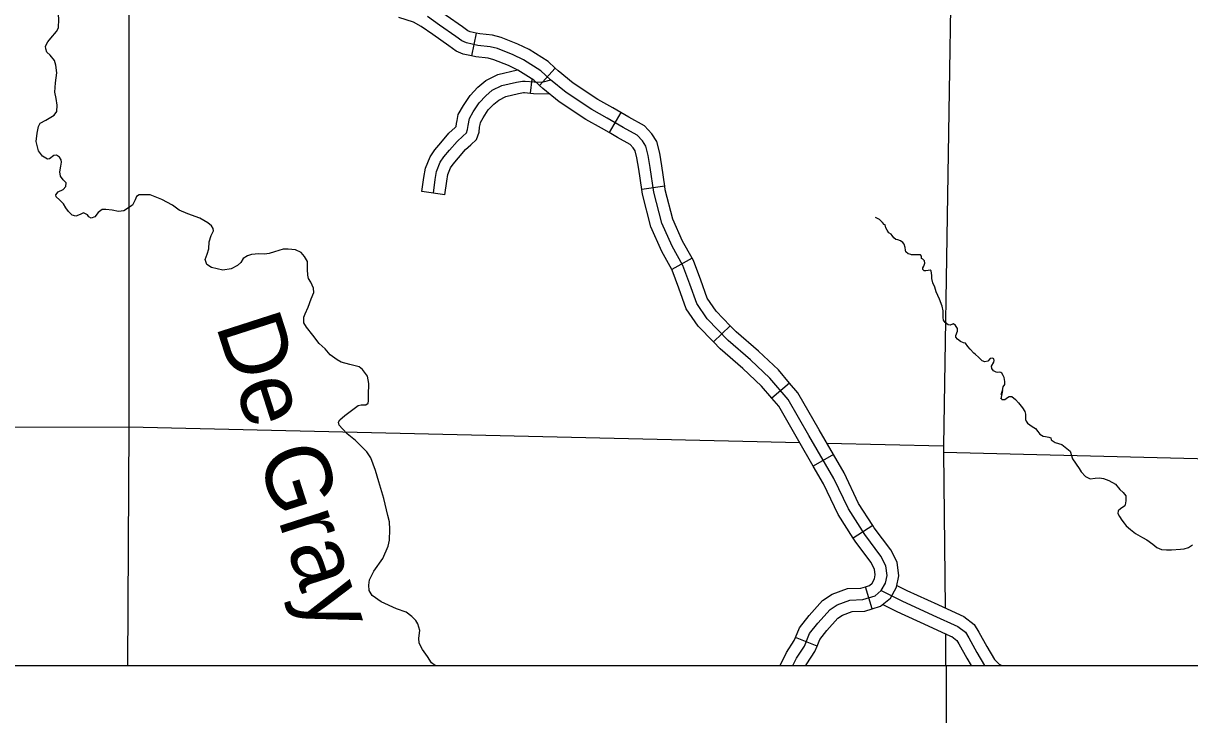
# Model space of a CAD drawing. Extents: x 1373862 to 1377080, y 1164775 to 1170415.
# Drawn here: x 1375030.3 to 1375152.2, y 1168588.7 to 1168661 of the extents above; entities that cross this region are included whole.
import ezdxf

# ---------------------------------------------------------------- set-up
doc = ezdxf.new("R2010")
doc.units = 0
for name, color, linetype in [('1', 7, 'Continuous'), ('Level 32', 7, 'Continuous'), ('Level 35', 7, 'Continuous'), ('Level 4', 7, 'Continuous'), ('Level 45', 7, 'Continuous'), ('Level 5', 7, 'Continuous'), ('R_Dimension', 7, 'Continuous')]:
    doc.layers.add(name, color=color, linetype=linetype)

msp = doc.modelspace()

# ---------------------------------------------------------------- linework, layer by layer
at = {"layer": '1'}
msp.add_lwpolyline([(1376107.39, 1169553.54), (1374750.71, 1169553.54), (1374750.71, 1168593.87), (1376107.39, 1168593.87)], close=True, dxfattribs=at)
at = {"layer": 'Level 32'}
for p, q in [((1375077.62, 1168659.94), (1375077.11, 1168657.57)), ((1375085.87, 1168656.27), (1375084.24, 1168654.47)), ((1375092.73, 1168651.63), (1375091.5, 1168649.54)), ((1375097.32, 1168643.96), (1375094.91, 1168643.61)), ((1375100.18, 1168636.44), (1375098.06, 1168635.24)), ((1375104.15, 1168629.37), (1375102.41, 1168627.68)), ((1375110.35, 1168623.39), (1375108.51, 1168621.81)), ((1375114.94, 1168615.93), (1375112.84, 1168614.71)), ((1375119.05, 1168608.49), (1375117, 1168607.19)), ((1375119.01, 1168599.79), (1375118.28, 1168602.11)), ((1375113.23, 1168595.89), (1375110.98, 1168596.82))]:
    msp.add_line(p, q, dxfattribs=at)
for points in [[(1375077.11, 1168657.57), (1375076.25, 1168657.75), (1375075.51, 1168658.05), (1375074.77, 1168658.62), (1375073.08, 1168659.78), (1375071.86, 1168660.64), (1375071.07, 1168661.09), (1375069.54, 1168661.56)], [(1375077.62, 1168659.94), (1375076.97, 1168660.08), (1375076.73, 1168660.18), (1375076.2, 1168660.59), (1375074.47, 1168661.78), (1375073.98, 1168662.12)], [(1375085.87, 1168656.27), (1375085.12, 1168656.96), (1375083.16, 1168658.21), (1375081.97, 1168658.78), (1375080.22, 1168659.48), (1375079.31, 1168659.72), (1375077.98, 1168659.86), (1375077.62, 1168659.94)], [(1375084.24, 1168654.47), (1375083.63, 1168655.02), (1375081.97, 1168656.08), (1375081, 1168656.56), (1375079.46, 1168657.16), (1375078.86, 1168657.32), (1375077.59, 1168657.46), (1375077.11, 1168657.57)], [(1375092.73, 1168651.63), (1375091.91, 1168652.12), (1375090.33, 1168653), (1375087.74, 1168654.72), (1375086.18, 1168655.99), (1375085.87, 1168656.27)], [(1375091.5, 1168649.54), (1375090.7, 1168650.01), (1375089.06, 1168650.93), (1375086.3, 1168652.76), (1375084.59, 1168654.14), (1375084.24, 1168654.47)], [(1375097.32, 1168643.96), (1375097, 1168646.09), (1375096.79, 1168647.41), (1375096.48, 1168648.6), (1375095.98, 1168649.41), (1375095.2, 1168650.26), (1375093.56, 1168651.15), (1375092.73, 1168651.63)], [(1375094.91, 1168643.61), (1375094.6, 1168645.73), (1375094.41, 1168646.91), (1375094.22, 1168647.63), (1375094.03, 1168647.94), (1375093.69, 1168648.32), (1375092.37, 1168649.03), (1375091.5, 1168649.54)], [(1375098.06, 1168635.24), (1375097.01, 1168637.12), (1375095.86, 1168639.69), (1375094.99, 1168643.1), (1375094.91, 1168643.61)], [(1375100.18, 1168636.44), (1375099.18, 1168638.21), (1375098.16, 1168640.49), (1375097.37, 1168643.58), (1375097.32, 1168643.96)], [(1375104.15, 1168629.37), (1375102.69, 1168630.88), (1375101.75, 1168632.26), (1375101.08, 1168634.14), (1375100.32, 1168636.19), (1375100.18, 1168636.44)], [(1375102.41, 1168627.68), (1375100.8, 1168629.34), (1375099.57, 1168631.15), (1375098.79, 1168633.31), (1375098.11, 1168635.17), (1375098.06, 1168635.24)], [(1375110.35, 1168623.39), (1375109.19, 1168624.75), (1375107.1, 1168626.73), (1375104.78, 1168628.72), (1375104.15, 1168629.37)], [(1375108.51, 1168621.81), (1375107.43, 1168623.07), (1375105.47, 1168624.92), (1375103.11, 1168626.95), (1375102.41, 1168627.68)], [(1375114.94, 1168615.93), (1375113.44, 1168618.51), (1375111.22, 1168622.37), (1375110.35, 1168623.39)], [(1375112.84, 1168614.71), (1375111.34, 1168617.3), (1375109.23, 1168620.96), (1375108.51, 1168621.81)], [(1375119.05, 1168608.49), (1375117.57, 1168610.82), (1375116.07, 1168613.99), (1375114.94, 1168615.93)], [(1375117, 1168607.19), (1375115.44, 1168609.64), (1375113.92, 1168612.86), (1375112.84, 1168614.71)], [(1375119.01, 1168599.79), (1375119.88, 1168600.07), (1375120.9, 1168600.91), (1375121.52, 1168602.06), (1375121.79, 1168603.24), (1375121.59, 1168604.67), (1375120.94, 1168605.96), (1375119.21, 1168608.25), (1375119.05, 1168608.49)], [(1375118.28, 1168602.11), (1375118.7, 1168602.24), (1375118.98, 1168602.48), (1375119.23, 1168602.93), (1375119.32, 1168603.34), (1375119.24, 1168603.93), (1375118.87, 1168604.67), (1375117.21, 1168606.86), (1375117, 1168607.19)], [(1375110.98, 1168596.82), (1375111.41, 1168597.83), (1375112.4, 1168599.09), (1375113.8, 1168600.68), (1375114.8, 1168601.32), (1375116.42, 1168601.93), (1375117.82, 1168601.97), (1375118.28, 1168602.11)], [(1375113.23, 1168595.89), (1375113.52, 1168596.59), (1375114.26, 1168597.54), (1375115.39, 1168598.81), (1375115.9, 1168599.14), (1375116.89, 1168599.51), (1375118.23, 1168599.55), (1375119.01, 1168599.79)], [(1375109.37, 1168593.87), (1375110.03, 1168595.25), (1375110.84, 1168596.48), (1375110.98, 1168596.82)], [(1375112.06, 1168593.87), (1375112.15, 1168594.05), (1375113, 1168595.34), (1375113.23, 1168595.89)]]:
    msp.add_lwpolyline(points, dxfattribs=at)
at = {"layer": 'Level 35'}
for points in [[(1375033.15, 1168659.42), (1375033.76, 1168660.1), (1375033.97, 1168660.48), (1375034, 1168661.39), (1375033.93, 1168662.27), (1375033.58, 1168663.83), (1375033.26, 1168664.86), (1375032.62, 1168665.87), (1375032.1, 1168666.5), (1375031.54, 1168667.06), (1375030.64, 1168667.66), (1375030.46, 1168667.73)], [(1375033.04, 1168646.82), (1375032.83, 1168646.76), (1375032.29, 1168647.09), (1375031.86, 1168647.65), (1375031.63, 1168648.62), (1375031.73, 1168649.5), (1375031.86, 1168650.19), (1375032.06, 1168650.53), (1375032.64, 1168650.86), (1375033.5, 1168651.37), (1375033.78, 1168651.76), (1375033.84, 1168652.41), (1375033.71, 1168653.12), (1375033.58, 1168653.76), (1375033.65, 1168654.73), (1375033.78, 1168655.79), (1375033.69, 1168656.6), (1375033.56, 1168657.08), (1375033.09, 1168657.64), (1375032.75, 1168657.94), (1375032.66, 1168658.31), (1375032.62, 1168658.56), (1375032.85, 1168659.02), (1375033.15, 1168659.42)], [(1375048.74, 1168640.61), (1375047.48, 1168641.05), (1375046.59, 1168641.44), (1375045.88, 1168641.98), (1375044.77, 1168642.56), (1375043.56, 1168643.03), (1375042.85, 1168643.03), (1375042.38, 1168643.05), (1375042.12, 1168642.88), (1375041.97, 1168642.54), (1375041.69, 1168641.95), (1375040.79, 1168641.37), (1375040.25, 1168641.31), (1375039.58, 1168641.46), (1375038.91, 1168641.5), (1375038.53, 1168641.52), (1375038.1, 1168641.2), (1375037.77, 1168640.73), (1375037.39, 1168640.6), (1375037.13, 1168640.73), (1375036.98, 1168640.96), (1375036.59, 1168641.16), (1375036.22, 1168640.98), (1375035.79, 1168640.83), (1375035.41, 1168640.92), (1375035, 1168641.29), (1375034.74, 1168641.7), (1375034.5, 1168642.1), (1375034.07, 1168642.54), (1375033.73, 1168642.82), (1375033.69, 1168643.03), (1375033.94, 1168643.37), (1375034.44, 1168643.61), (1375034.74, 1168643.91), (1375034.76, 1168644.3), (1375034.44, 1168644.6), (1375034.18, 1168645.01), (1375034.09, 1168645.44), (1375034.2, 1168646.04), (1375034.27, 1168646.45), (1375034.25, 1168646.71), (1375034.07, 1168646.97), (1375033.75, 1168647.19), (1375033.47, 1168647.16), (1375033.04, 1168646.82)], [(1375060.37, 1168632.18), (1375060.64, 1168632.86), (1375060.62, 1168633.31), (1375060.34, 1168633.93), (1375060.1, 1168634.3), (1375060.01, 1168634.67), (1375059.99, 1168635.25), (1375059.99, 1168635.74), (1375059.99, 1168636.09), (1375059.69, 1168636.62), (1375059.32, 1168637.03), (1375058.74, 1168637.31), (1375057.97, 1168637.36), (1375057.43, 1168637.38), (1375056.53, 1168637.1), (1375055.99, 1168636.93), (1375055.5, 1168636.84), (1375054.91, 1168636.88), (1375054.12, 1168636.82), (1375053.71, 1168636.69), (1375053.26, 1168636.41), (1375053.02, 1168635.98), (1375052.68, 1168635.66), (1375052.01, 1168635.31), (1375051.13, 1168635.16), (1375049.97, 1168635.46), (1375049.45, 1168635.78), (1375049.3, 1168636.28), (1375049.49, 1168636.84), (1375049.67, 1168637.42), (1375049.71, 1168638.13), (1375049.92, 1168638.8), (1375050.16, 1168639.27), (1375050.12, 1168639.53), (1375049.97, 1168639.81), (1375049.56, 1168640.13), (1375048.74, 1168640.61)], [(1375131.47, 1168625.14), (1375131.7, 1168625.57), (1375131.74, 1168625.74), (1375131.72, 1168625.93), (1375131.57, 1168625.97), (1375131.34, 1168625.95), (1375131.07, 1168625.68), (1375130.75, 1168625.61), (1375130.5, 1168625.7), (1375130.1, 1168626.08), (1375129.78, 1168626.37), (1375129.63, 1168626.52), (1375129.25, 1168626.92), (1375129, 1168627.22), (1375128.74, 1168627.56), (1375128.55, 1168627.6), (1375128.22, 1168627.71), (1375127.9, 1168627.96), (1375127.75, 1168628.17), (1375127.75, 1168628.34), (1375127.9, 1168628.81), (1375127.9, 1168629.08), (1375127.69, 1168629.4), (1375127.48, 1168629.57), (1375127.39, 1168629.55), (1375127.14, 1168629.42), (1375126.95, 1168629.48), (1375126.61, 1168629.71), (1375126.46, 1168629.95), (1375126.42, 1168630.24), (1375126.42, 1168630.56), (1375126.4, 1168630.94), (1375126.31, 1168631.43), (1375126.02, 1168632.16), (1375125.68, 1168632.92), (1375125.55, 1168633.4), (1375125.34, 1168633.87), (1375125.24, 1168634.31), (1375125.22, 1168634.61), (1375125.15, 1168635.1), (1375125.05, 1168635.18), (1375124.86, 1168635.14), (1375124.6, 1168635.1), (1375124.43, 1168635.12), (1375124.29, 1168635.24), (1375124.29, 1168635.41), (1375124.39, 1168635.6), (1375124.48, 1168635.92), (1375124.46, 1168636.15), (1375124.29, 1168636.32), (1375124.16, 1168636.39), (1375124.14, 1168636.47), (1375124.14, 1168636.64), (1375124.04, 1168636.77), (1375123.91, 1168636.77), (1375123.64, 1168636.79), (1375123.42, 1168636.77), (1375123.11, 1168636.79), (1375123.02, 1168636.81), (1375122.77, 1168636.87), (1375122.52, 1168637.08), (1375122.47, 1168637.25), (1375122.45, 1168637.55), (1375122.33, 1168637.89), (1375122.2, 1168638.06), (1375121.95, 1168638.25), (1375121.67, 1168638.33), (1375121.48, 1168638.37), (1375121.25, 1168638.56), (1375121.08, 1168638.8), (1375120.97, 1168638.92), (1375120.72, 1168639.09), (1375120.55, 1168639.35), (1375120.42, 1168639.6), (1375120.34, 1168639.9), (1375120.26, 1168639.96), (1375120.06, 1168640.15), (1375119.75, 1168640.47), (1375119.35, 1168640.68)], [(1375065.28, 1168621.03), (1375065.58, 1168621.11), (1375065.84, 1168621.11), (1375066.07, 1168621.11), (1375066.33, 1168621.28), (1375066.37, 1168621.52), (1375066.37, 1168622.04), (1375066.35, 1168622.51), (1375066.4, 1168622.94), (1375066.4, 1168623.33), (1375066.27, 1168624.1), (1375065.75, 1168624.79), (1375065.39, 1168625.09), (1375064.4, 1168625.33), (1375063.49, 1168625.55), (1375063.1, 1168625.8), (1375062.37, 1168626.32), (1375061.84, 1168626.95), (1375061.19, 1168627.51), (1375060.54, 1168628.37), (1375059.88, 1168629.21), (1375059.62, 1168629.66), (1375059.62, 1168630.05), (1375059.6, 1168630.28), (1375059.73, 1168630.63), (1375060.05, 1168631.3), (1375060.37, 1168632.18)], [(1375132.46, 1168622.2), (1375132.63, 1168622.62), (1375132.69, 1168622.98), (1375132.84, 1168623.23), (1375132.84, 1168623.55), (1375132.8, 1168623.95), (1375132.69, 1168624.16), (1375132.55, 1168624.4), (1375132.44, 1168624.5), (1375132.34, 1168624.52), (1375132.1, 1168624.5), (1375131.96, 1168624.52), (1375131.66, 1168624.67), (1375131.51, 1168624.9), (1375131.47, 1168625.14)], [(1375132.63, 1168622.62), (1375132.44, 1168621.75), (1375132.46, 1168621.8), (1375132.55, 1168621.67), (1375132.84, 1168621.67), (1375133.12, 1168621.88), (1375133.31, 1168621.99), (1375133.58, 1168621.97), (1375133.98, 1168621.65), (1375134.28, 1168621.31), (1375134.7, 1168620.78), (1375134.93, 1168620.4), (1375135, 1168620.13), (1375135, 1168619.79), (1375135.02, 1168619.58), (1375135.08, 1168619.39), (1375135.21, 1168619.2), (1375135.72, 1168618.84), (1375136.05, 1168618.65), (1375136.29, 1168618.33), (1375136.52, 1168618.03), (1375136.88, 1168617.84), (1375137.11, 1168617.8), (1375137.47, 1168617.74), (1375137.66, 1168617.65), (1375137.7, 1168617.44), (1375138.12, 1168617.17), (1375138.8, 1168616.98)], [(1375068.38, 1168609.56), (1375067.95, 1168611.31), (1375067.45, 1168613.05), (1375067.08, 1168614.26), (1375066.61, 1168615.59), (1375066.2, 1168616.2), (1375065.58, 1168616.8), (1375065, 1168617.38), (1375064.12, 1168618.09), (1375063.66, 1168618.59), (1375063.28, 1168618.99), (1375063.21, 1168619.3), (1375063.36, 1168619.55), (1375063.88, 1168620.01), (1375064.87, 1168620.74), (1375065.28, 1168621.03)], [(1375138.8, 1168616.98), (1375139.69, 1168616.28), (1375139.92, 1168615.48), (1375140.62, 1168614.46), (1375140.85, 1168614.12), (1375141.29, 1168613.62), (1375141.78, 1168613.38), (1375142.31, 1168613.45), (1375142.75, 1168613.47), (1375143.17, 1168613.42), (1375143.72, 1168613.19), (1375144.42, 1168612.83), (1375144.88, 1168612.26), (1375145.24, 1168611.94), (1375145.5, 1168611.61), (1375145.5, 1168611.13), (1375145.47, 1168610.83), (1375145.39, 1168610.56), (1375144.93, 1168610.24), (1375144.69, 1168610.05), (1375144.67, 1168609.75), (1375144.84, 1168609.44), (1375145.09, 1168609.06), (1375145.33, 1168608.74), (1375145.52, 1168608.46), (1375145.98, 1168608.1), (1375146.51, 1168607.68), (1375147.25, 1168607.24), (1375147.71, 1168607.01), (1375148.34, 1168606.54), (1375148.74, 1168606.2), (1375149.23, 1168606.01), (1375149.76, 1168605.95), (1375150.29, 1168605.97), (1375151.2, 1168606.03), (1375151.6, 1168606.07), (1375152.04, 1168606.22), (1375152.46, 1168606.48)], [(1375067.67, 1168600.52), (1375066.76, 1168601.18), (1375066.44, 1168601.7), (1375066.4, 1168602.28), (1375066.46, 1168602.84), (1375066.91, 1168603.74), (1375067.86, 1168605.06), (1375068.4, 1168606.35), (1375068.57, 1168606.99), (1375068.59, 1168608.09), (1375068.57, 1168608.89), (1375068.38, 1168609.56)], [(1375073.34, 1168593.87), (1375072.94, 1168594.15), (1375072.53, 1168594.82), (1375072.01, 1168595.57), (1375071.67, 1168596.22), (1375071.62, 1168596.73), (1375071.71, 1168597.53), (1375071.5, 1168598.24), (1375071.32, 1168598.59), (1375070.89, 1168599), (1375070.31, 1168599.45), (1375069.3, 1168599.81), (1375067.67, 1168600.52)]]:
    msp.add_lwpolyline(points, dxfattribs=at)
at = {"layer": 'Level 4'}
for points in [[(1375128.05, 1168720.45), (1375127.81, 1168703.12), (1375127.79, 1168701.88), (1375126.45, 1168616.81), (1375126.45, 1168616.15), (1375126.61, 1168599.9)], [(1375126.64, 1168597.21), (1375126.67, 1168593.87)]]:
    msp.add_lwpolyline(points, dxfattribs=at)
at = {"layer": 'Level 45'}
for p, q in [((1375083.3, 1168653.66), (1375083.45, 1168655.14)), ((1375074.34, 1168643.06), (1375071.94, 1168643.4))]:
    msp.add_line(p, q, dxfattribs=at)
for points in [[(1375085.39, 1168655.07), (1375084.37, 1168655.99), (1375082.57, 1168657.14), (1375081.49, 1168657.67), (1375079.84, 1168658.32), (1375079.08, 1168658.52), (1375077.78, 1168658.66), (1375076.61, 1168658.92), (1375076.12, 1168659.12), (1375075.49, 1168659.6), (1375073.77, 1168660.78), (1375072.51, 1168661.66)], [(1375075.63, 1168650.82), (1375075.74, 1168651.43), (1375076.28, 1168652.37), (1375076.97, 1168653.43), (1375077.78, 1168654.28), (1375078.63, 1168655), (1375079.88, 1168655.61), (1375081.93, 1168656.1)], [(1375073.48, 1168645.49), (1375073.86, 1168646.45), (1375074.24, 1168647), (1375074.84, 1168647.7), (1375075.62, 1168648.62), (1375076.23, 1168649.18), (1375076.59, 1168649.51), (1375076.72, 1168649.87), (1375076.77, 1168650.3), (1375076.9, 1168651.01), (1375077.31, 1168651.73), (1375077.93, 1168652.67), (1375078.61, 1168653.4), (1375079.3, 1168653.97), (1375080.29, 1168654.46), (1375081.81, 1168654.82), (1375082.46, 1168654.93), (1375082.73, 1168654.93), (1375083.67, 1168654.84), (1375084.47, 1168654.82), (1375085.03, 1168654.95), (1375085.39, 1168655.07)], [(1375095.8, 1168645.91), (1375095.6, 1168647.16), (1375095.35, 1168648.12), (1375095.01, 1168648.68), (1375094.45, 1168649.29), (1375092.96, 1168650.09), (1375091.3, 1168651.06), (1375089.7, 1168651.97), (1375087.02, 1168653.74), (1375085.39, 1168655.07)], [(1375078.02, 1168650.39), (1375078.06, 1168650.59), (1375078.35, 1168651.1), (1375078.88, 1168651.92), (1375079.45, 1168652.51), (1375079.97, 1168652.95), (1375080.71, 1168653.31), (1375082.05, 1168653.63), (1375082.56, 1168653.72), (1375082.67, 1168653.72), (1375083.3, 1168653.66)], [(1375083.3, 1168653.66), (1375083.6, 1168653.63), (1375085.28, 1168653.59)], [(1375071.94, 1168643.4), (1375072.14, 1168644.84), (1375072.31, 1168645.83), (1375072.79, 1168647.03), (1375073.28, 1168647.74), (1375073.91, 1168648.48), (1375074.74, 1168649.47), (1375075.41, 1168650.08), (1375075.53, 1168650.19), (1375075.57, 1168650.49), (1375075.63, 1168650.82)], [(1375074.34, 1168643.06), (1375074.54, 1168644.47), (1375074.66, 1168645.16), (1375074.94, 1168645.87), (1375075.21, 1168646.25), (1375075.77, 1168646.92), (1375076.49, 1168647.78), (1375077.05, 1168648.28), (1375077.63, 1168648.81), (1375077.91, 1168649.59), (1375077.97, 1168650.12), (1375078.02, 1168650.39)], [(1375103.95, 1168627.83), (1375101.74, 1168630.11), (1375100.66, 1168631.7), (1375099.94, 1168633.73), (1375099.21, 1168635.68), (1375098.09, 1168637.67), (1375097.01, 1168640.09), (1375096.18, 1168643.34), (1375095.8, 1168645.91)], [(1375073.14, 1168643.23), (1375073.34, 1168644.66), (1375073.48, 1168645.49)], [(1375114.99, 1168613.42), (1375112.39, 1168617.91), (1375110.22, 1168621.67), (1375108.31, 1168623.91), (1375106.29, 1168625.82), (1375103.95, 1168627.83)], [(1375111.09, 1168594.65), (1375111.92, 1168595.91), (1375112.46, 1168597.21), (1375113.33, 1168598.32), (1375114.59, 1168599.74), (1375115.35, 1168600.23), (1375116.65, 1168600.72), (1375118.03, 1168600.76), (1375119.29, 1168601.15), (1375119.94, 1168601.7), (1375120.37, 1168602.49), (1375120.55, 1168603.29), (1375120.41, 1168604.3), (1375119.9, 1168605.31), (1375118.21, 1168607.55), (1375116.51, 1168610.23), (1375114.99, 1168613.42)], [(1375121.56, 1168602.24), (1375122.62, 1168601.72), (1375125.85, 1168600.24), (1375128.19, 1168599.17)], [(1375119.94, 1168601.7), (1375122.09, 1168600.62), (1375125.34, 1168599.14), (1375127.95, 1168597.95), (1375128.74, 1168597.35), (1375129.1, 1168596.77), (1375129.93, 1168595.25), (1375130.74, 1168593.87)], [(1375120.11, 1168600.25), (1375121.57, 1168599.53), (1375124.84, 1168598.03), (1375127.18, 1168596.96)], [(1375128.19, 1168599.17), (1375128.57, 1168599), (1375129.65, 1168598.18), (1375130.15, 1168597.38), (1375130.99, 1168595.85), (1375131.77, 1168594.52), (1375132.26, 1168594.02), (1375132.53, 1168593.87)], [(1375127.18, 1168596.96), (1375127.32, 1168596.9), (1375127.83, 1168596.51), (1375128.05, 1168596.15), (1375128.87, 1168594.65), (1375129.33, 1168593.87)], [(1375110.71, 1168593.87), (1375111.09, 1168594.65)]]:
    msp.add_lwpolyline(points, dxfattribs=at)
at = {"layer": 'Level 5'}
for points in [[(1375041.33, 1168663.7), (1375041.33, 1168618.8)], [(1374956.37, 1168618.72), (1375041.33, 1168618.8)], [(1375041.33, 1168618.8), (1375041.17, 1168593.87)], [(1375041.33, 1168618.8), (1375111.42, 1168617.16)], [(1375114.26, 1168617.1), (1375126.45, 1168616.81)], [(1375126.45, 1168616.15), (1375199, 1168614.34)]]:
    msp.add_lwpolyline(points, dxfattribs=at)
at = {"layer": 'R_Dimension'}
msp.add_line((1375126.8, 1168533.87), (1375126.77, 1168593.87), dxfattribs=at)

# ---------------------------------------------------------------- texts
at = {"layer": 'Level 35'}
msp.add_text('De Gray', height=6.843, rotation=287.8154, dxfattribs=at).set_placement((1375050.37, 1168629.42))

doc.saveas('drawing.dxf')
